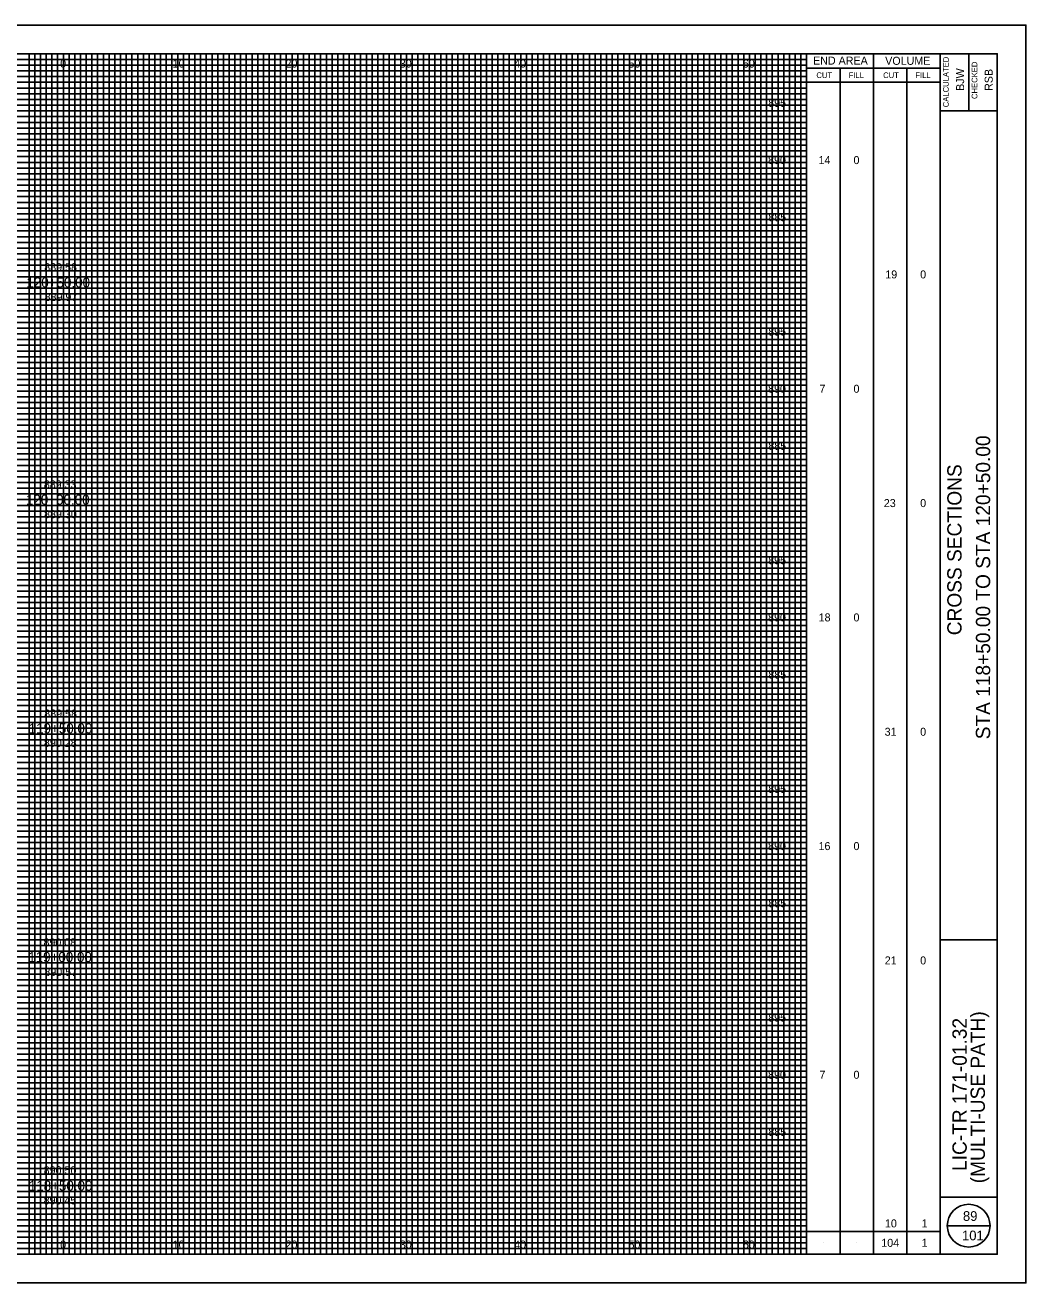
# Model space of a CAD drawing. Extents: x -10 to 160, y -2 to 3672.
# Drawn here: x 72.5 to 160, y 2297.5 to 2407.5 of the extents above; entities that cross this region are included whole.
import ezdxf

# ---------------------------------------------------------------- set-up
doc = ezdxf.new("R2010")
doc.units = 0
for name, color, linetype in [('SH_Border', 7, 'Continuous'), ('SH_Cut_Line', 7, 'Continuous'), ('SH_Data', 7, 'Continuous'), ('SH_Major_Grid_Line', 7, 'Continuous'), ('SH_Minor_Grid_Line', 7, 'Continuous'), ('SH_Text', 7, 'Continuous'), ('TX_P_10', 7, 'Continuous'), ('TX_X_10', 7, 'Continuous')]:
    doc.layers.add(name, color=color, linetype=linetype)

msp = doc.modelspace()

# ---------------------------------------------------------------- linework, layer by layer
at = {"layer": 'SH_Border'}
for p, q in [((152.5, 2300), (152.5, 2405)), ((155, 2405), (155, 2400)), ((152.5, 2400), (157.5, 2400)), ((152.5, 2327.5), (157.5, 2327.5)), ((152.5, 2305), (157.5, 2305))]:
    msp.add_line(p, q, dxfattribs=at)
msp.add_lwpolyline([(0, 2405), (157.5, 2405), (157.5, 2300), (0, 2300)], close=True, dxfattribs=at)
at = {"layer": 'SH_Cut_Line'}
msp.add_lwpolyline([(-10, 2297.5), (160, 2297.5), (160, 2407.5), (-10, 2407.5)], close=True, dxfattribs=at)
at = {"layer": 'SH_Data'}
for p, q in [((140.83, 2300), (140.83, 2405)), ((146.67, 2300), (146.67, 2405)), ((140.83, 2403.75), (152.5, 2403.75)), ((143.75, 2300), (143.75, 2403.75)), ((149.58, 2300), (149.58, 2403.75)), ((140.83, 2402.5), (152.5, 2402.5)), ((153.12, 2302.5), (156.88, 2302.5)), ((140.83, 2302), (152.5, 2302)), ((142.29, 2301), (142.29, 2301)), ((145.21, 2301), (145.21, 2301)), ((148.12, 2301), (148.12, 2301)), ((151.04, 2301), (151.04, 2301))]:
    msp.add_line(p, q, dxfattribs=at)
msp.add_circle((155, 2302.5), 1.87, dxfattribs=at)
at = {"layer": 'SH_Major_Grid_Line'}
for p, q in [((75.83, 2300), (75.83, 2405)), ((80.83, 2300), (80.83, 2405)), ((85.83, 2300), (85.83, 2405)), ((90.83, 2300), (90.83, 2405)), ((95.83, 2300), (95.83, 2405)), ((100.83, 2300), (100.83, 2405)), ((105.83, 2300), (105.83, 2405)), ((110.83, 2300), (110.83, 2405)), ((115.83, 2300), (115.83, 2405)), ((120.83, 2300), (120.83, 2405)), ((125.83, 2300), (125.83, 2405)), ((130.83, 2300), (130.83, 2405)), ((135.83, 2300), (135.83, 2405)), ((5.83, 2400), (140.83, 2400)), ((5.83, 2395), (140.83, 2395)), ((5.83, 2390), (140.83, 2390)), ((5.83, 2385), (140.83, 2385)), ((5.83, 2380), (140.83, 2380)), ((5.83, 2375), (140.83, 2375)), ((5.83, 2370), (140.83, 2370)), ((5.83, 2365), (140.83, 2365)), ((5.83, 2360), (140.83, 2360)), ((5.83, 2355), (140.83, 2355)), ((5.83, 2350), (140.83, 2350)), ((5.83, 2345), (140.83, 2345)), ((5.83, 2340), (140.83, 2340)), ((5.83, 2335), (140.83, 2335)), ((5.83, 2330), (140.83, 2330)), ((5.83, 2325), (140.83, 2325)), ((5.83, 2320), (140.83, 2320)), ((5.83, 2315), (140.83, 2315)), ((5.83, 2310), (140.83, 2310)), ((5.83, 2305), (140.83, 2305))]:
    msp.add_line(p, q, dxfattribs=at)
at = {"layer": 'SH_Minor_Grid_Line'}
for p, q in [((72.83, 2300), (72.83, 2405)), ((73.33, 2300), (73.33, 2405)), ((73.83, 2300), (73.83, 2405)), ((74.33, 2300), (74.33, 2405)), ((74.83, 2300), (74.83, 2405)), ((75.33, 2300), (75.33, 2405)), ((76.33, 2300), (76.33, 2405)), ((76.83, 2300), (76.83, 2405)), ((77.33, 2300), (77.33, 2405)), ((77.83, 2300), (77.83, 2405)), ((78.33, 2300), (78.33, 2405)), ((78.83, 2300), (78.83, 2405)), ((79.33, 2300), (79.33, 2405)), ((79.83, 2300), (79.83, 2405)), ((80.33, 2300), (80.33, 2405)), ((81.33, 2300), (81.33, 2405)), ((81.83, 2300), (81.83, 2405)), ((82.33, 2300), (82.33, 2405)), ((82.83, 2300), (82.83, 2405)), ((83.33, 2300), (83.33, 2405)), ((83.83, 2300), (83.83, 2405)), ((84.33, 2300), (84.33, 2405)), ((84.83, 2300), (84.83, 2405)), ((85.33, 2300), (85.33, 2405)), ((86.33, 2300), (86.33, 2405)), ((86.83, 2300), (86.83, 2405)), ((87.33, 2300), (87.33, 2405)), ((87.83, 2300), (87.83, 2405)), ((88.33, 2300), (88.33, 2405)), ((88.83, 2300), (88.83, 2405)), ((89.33, 2300), (89.33, 2405)), ((89.83, 2300), (89.83, 2405)), ((90.33, 2300), (90.33, 2405)), ((91.33, 2300), (91.33, 2405)), ((91.83, 2300), (91.83, 2405)), ((92.33, 2300), (92.33, 2405)), ((92.83, 2300), (92.83, 2405)), ((93.33, 2300), (93.33, 2405)), ((93.83, 2300), (93.83, 2405)), ((94.33, 2300), (94.33, 2405)), ((94.83, 2300), (94.83, 2405)), ((95.33, 2300), (95.33, 2405)), ((96.33, 2300), (96.33, 2405)), ((96.83, 2300), (96.83, 2405)), ((97.33, 2300), (97.33, 2405)), ((97.83, 2300), (97.83, 2405)), ((98.33, 2300), (98.33, 2405)), ((98.83, 2300), (98.83, 2405)), ((99.33, 2300), (99.33, 2405)), ((99.83, 2300), (99.83, 2405)), ((100.33, 2300), (100.33, 2405)), ((101.33, 2300), (101.33, 2405)), ((101.83, 2300), (101.83, 2405)), ((102.33, 2300), (102.33, 2405)), ((102.83, 2300), (102.83, 2405)), ((103.33, 2300), (103.33, 2405)), ((103.83, 2300), (103.83, 2405)), ((104.33, 2300), (104.33, 2405)), ((104.83, 2300), (104.83, 2405)), ((105.33, 2300), (105.33, 2405)), ((106.33, 2300), (106.33, 2405)), ((106.83, 2300), (106.83, 2405)), ((107.33, 2300), (107.33, 2405)), ((107.83, 2300), (107.83, 2405)), ((108.33, 2300), (108.33, 2405)), ((108.83, 2300), (108.83, 2405)), ((109.33, 2300), (109.33, 2405)), ((109.83, 2300), (109.83, 2405)), ((110.33, 2300), (110.33, 2405)), ((111.33, 2300), (111.33, 2405)), ((111.83, 2300), (111.83, 2405)), ((112.33, 2300), (112.33, 2405)), ((112.83, 2300), (112.83, 2405)), ((113.33, 2300), (113.33, 2405)), ((113.83, 2300), (113.83, 2405)), ((114.33, 2300), (114.33, 2405)), ((114.83, 2300), (114.83, 2405)), ((115.33, 2300), (115.33, 2405)), ((116.33, 2300), (116.33, 2405)), ((116.83, 2300), (116.83, 2405)), ((117.33, 2300), (117.33, 2405)), ((117.83, 2300), (117.83, 2405)), ((118.33, 2300), (118.33, 2405)), ((118.83, 2300), (118.83, 2405)), ((119.33, 2300), (119.33, 2405)), ((119.83, 2300), (119.83, 2405)), ((120.33, 2300), (120.33, 2405)), ((121.33, 2300), (121.33, 2405)), ((121.83, 2300), (121.83, 2405)), ((122.33, 2300), (122.33, 2405)), ((122.83, 2300), (122.83, 2405)), ((123.33, 2300), (123.33, 2405)), ((123.83, 2300), (123.83, 2405)), ((124.33, 2300), (124.33, 2405)), ((124.83, 2300), (124.83, 2405)), ((125.33, 2300), (125.33, 2405)), ((126.33, 2300), (126.33, 2405)), ((126.83, 2300), (126.83, 2405)), ((127.33, 2300), (127.33, 2405)), ((127.83, 2300), (127.83, 2405)), ((128.33, 2300), (128.33, 2405)), ((128.83, 2300), (128.83, 2405)), ((129.33, 2300), (129.33, 2405)), ((129.83, 2300), (129.83, 2405)), ((130.33, 2300), (130.33, 2405)), ((131.33, 2300), (131.33, 2405)), ((131.83, 2300), (131.83, 2405)), ((132.33, 2300), (132.33, 2405)), ((132.83, 2300), (132.83, 2405)), ((133.33, 2300), (133.33, 2405)), ((133.83, 2300), (133.83, 2405)), ((134.33, 2300), (134.33, 2405)), ((134.83, 2300), (134.83, 2405)), ((135.33, 2300), (135.33, 2405)), ((136.33, 2300), (136.33, 2405)), ((136.83, 2300), (136.83, 2405)), ((137.33, 2300), (137.33, 2405)), ((137.83, 2300), (137.83, 2405)), ((138.33, 2300), (138.33, 2405)), ((138.83, 2300), (138.83, 2405)), ((139.33, 2300), (139.33, 2405)), ((139.83, 2300), (139.83, 2405)), ((140.33, 2300), (140.33, 2405)), ((5.83, 2404.5), (140.83, 2404.5)), ((5.83, 2404), (140.83, 2404)), ((5.83, 2403.5), (140.83, 2403.5)), ((5.83, 2403), (140.83, 2403)), ((5.83, 2402.5), (140.83, 2402.5)), ((5.83, 2402), (140.83, 2402)), ((5.83, 2401.5), (140.83, 2401.5)), ((5.83, 2401), (140.83, 2401)), ((5.83, 2400.5), (140.83, 2400.5)), ((5.83, 2399.5), (140.83, 2399.5)), ((5.83, 2399), (140.83, 2399)), ((5.83, 2398.5), (140.83, 2398.5)), ((5.83, 2398), (140.83, 2398)), ((5.83, 2397.5), (140.83, 2397.5)), ((5.83, 2397), (140.83, 2397)), ((5.83, 2396.5), (140.83, 2396.5)), ((5.83, 2396), (140.83, 2396)), ((5.83, 2395.5), (140.83, 2395.5)), ((5.83, 2394.5), (140.83, 2394.5)), ((5.83, 2394), (140.83, 2394)), ((5.83, 2393.5), (140.83, 2393.5)), ((5.83, 2393), (140.83, 2393)), ((5.83, 2392.5), (140.83, 2392.5)), ((5.83, 2392), (140.83, 2392)), ((5.83, 2391.5), (140.83, 2391.5)), ((5.83, 2391), (140.83, 2391)), ((5.83, 2390.5), (140.83, 2390.5)), ((5.83, 2389.5), (140.83, 2389.5)), ((5.83, 2389), (140.83, 2389)), ((5.83, 2388.5), (140.83, 2388.5)), ((5.83, 2388), (140.83, 2388)), ((5.83, 2387.5), (140.83, 2387.5)), ((5.83, 2387), (140.83, 2387)), ((5.83, 2386.5), (140.83, 2386.5)), ((5.83, 2386), (140.83, 2386)), ((5.83, 2385.5), (140.83, 2385.5)), ((5.83, 2384.5), (140.83, 2384.5)), ((5.83, 2384), (140.83, 2384)), ((5.83, 2383.5), (140.83, 2383.5)), ((5.83, 2383), (140.83, 2383)), ((5.83, 2382.5), (140.83, 2382.5)), ((5.83, 2382), (140.83, 2382)), ((5.83, 2381.5), (140.83, 2381.5)), ((5.83, 2381), (140.83, 2381)), ((5.83, 2380.5), (140.83, 2380.5)), ((5.83, 2379.5), (140.83, 2379.5)), ((5.83, 2379), (140.83, 2379)), ((5.83, 2378.5), (140.83, 2378.5)), ((5.83, 2378), (140.83, 2378)), ((5.83, 2377.5), (140.83, 2377.5)), ((5.83, 2377), (140.83, 2377)), ((5.83, 2376.5), (140.83, 2376.5)), ((5.83, 2376), (140.83, 2376)), ((5.83, 2375.5), (140.83, 2375.5)), ((5.83, 2374.5), (140.83, 2374.5)), ((5.83, 2374), (140.83, 2374)), ((5.83, 2373.5), (140.83, 2373.5)), ((5.83, 2373), (140.83, 2373)), ((5.83, 2372.5), (140.83, 2372.5)), ((5.83, 2372), (140.83, 2372)), ((5.83, 2371.5), (140.83, 2371.5)), ((5.83, 2371), (140.83, 2371)), ((5.83, 2370.5), (140.83, 2370.5)), ((5.83, 2369.5), (140.83, 2369.5)), ((5.83, 2369), (140.83, 2369)), ((5.83, 2368.5), (140.83, 2368.5)), ((5.83, 2368), (140.83, 2368)), ((5.83, 2367.5), (140.83, 2367.5)), ((5.83, 2367), (140.83, 2367)), ((5.83, 2366.5), (140.83, 2366.5)), ((5.83, 2366), (140.83, 2366)), ((5.83, 2365.5), (140.83, 2365.5)), ((5.83, 2364.5), (140.83, 2364.5)), ((5.83, 2364), (140.83, 2364)), ((5.83, 2363.5), (140.83, 2363.5)), ((5.83, 2363), (140.83, 2363)), ((5.83, 2362.5), (140.83, 2362.5)), ((5.83, 2362), (140.83, 2362)), ((5.83, 2361.5), (140.83, 2361.5)), ((5.83, 2361), (140.83, 2361)), ((5.83, 2360.5), (140.83, 2360.5)), ((5.83, 2359.5), (140.83, 2359.5)), ((5.83, 2359), (140.83, 2359)), ((5.83, 2358.5), (140.83, 2358.5)), ((5.83, 2358), (140.83, 2358)), ((5.83, 2357.5), (140.83, 2357.5)), ((5.83, 2357), (140.83, 2357)), ((5.83, 2356.5), (140.83, 2356.5)), ((5.83, 2356), (140.83, 2356)), ((5.83, 2355.5), (140.83, 2355.5)), ((5.83, 2354.5), (140.83, 2354.5)), ((5.83, 2354), (140.83, 2354)), ((5.83, 2353.5), (140.83, 2353.5)), ((5.83, 2353), (140.83, 2353)), ((5.83, 2352.5), (140.83, 2352.5)), ((5.83, 2352), (140.83, 2352)), ((5.83, 2351.5), (140.83, 2351.5)), ((5.83, 2351), (140.83, 2351)), ((5.83, 2350.5), (140.83, 2350.5)), ((5.83, 2349.5), (140.83, 2349.5)), ((5.83, 2349), (140.83, 2349)), ((5.83, 2348.5), (140.83, 2348.5)), ((5.83, 2348), (140.83, 2348)), ((5.83, 2347.5), (140.83, 2347.5)), ((5.83, 2347), (140.83, 2347)), ((5.83, 2346.5), (140.83, 2346.5)), ((5.83, 2346), (140.83, 2346)), ((5.83, 2345.5), (140.83, 2345.5)), ((5.83, 2344.5), (140.83, 2344.5)), ((5.83, 2344), (140.83, 2344)), ((5.83, 2343.5), (140.83, 2343.5)), ((5.83, 2343), (140.83, 2343)), ((5.83, 2342.5), (140.83, 2342.5)), ((5.83, 2342), (140.83, 2342)), ((5.83, 2341.5), (140.83, 2341.5)), ((5.83, 2341), (140.83, 2341)), ((5.83, 2340.5), (140.83, 2340.5)), ((5.83, 2339.5), (140.83, 2339.5)), ((5.83, 2339), (140.83, 2339)), ((5.83, 2338.5), (140.83, 2338.5)), ((5.83, 2338), (140.83, 2338)), ((5.83, 2337.5), (140.83, 2337.5)), ((5.83, 2337), (140.83, 2337)), ((5.83, 2336.5), (140.83, 2336.5)), ((5.83, 2336), (140.83, 2336)), ((5.83, 2335.5), (140.83, 2335.5)), ((5.83, 2334.5), (140.83, 2334.5)), ((5.83, 2334), (140.83, 2334)), ((5.83, 2333.5), (140.83, 2333.5)), ((5.83, 2333), (140.83, 2333)), ((5.83, 2332.5), (140.83, 2332.5)), ((5.83, 2332), (140.83, 2332)), ((5.83, 2331.5), (140.83, 2331.5)), ((5.83, 2331), (140.83, 2331)), ((5.83, 2330.5), (140.83, 2330.5)), ((5.83, 2329.5), (140.83, 2329.5)), ((5.83, 2329), (140.83, 2329)), ((5.83, 2328.5), (140.83, 2328.5)), ((5.83, 2328), (140.83, 2328)), ((5.83, 2327.5), (140.83, 2327.5)), ((5.83, 2327), (140.83, 2327)), ((5.83, 2326.5), (140.83, 2326.5)), ((5.83, 2326), (140.83, 2326)), ((5.83, 2325.5), (140.83, 2325.5)), ((5.83, 2324.5), (140.83, 2324.5)), ((5.83, 2324), (140.83, 2324)), ((5.83, 2323.5), (140.83, 2323.5)), ((5.83, 2323), (140.83, 2323)), ((5.83, 2322.5), (140.83, 2322.5)), ((5.83, 2322), (140.83, 2322)), ((5.83, 2321.5), (140.83, 2321.5)), ((5.83, 2321), (140.83, 2321)), ((5.83, 2320.5), (140.83, 2320.5)), ((5.83, 2319.5), (140.83, 2319.5)), ((5.83, 2319), (140.83, 2319)), ((5.83, 2318.5), (140.83, 2318.5)), ((5.83, 2318), (140.83, 2318)), ((5.83, 2317.5), (140.83, 2317.5)), ((5.83, 2317), (140.83, 2317)), ((5.83, 2316.5), (140.83, 2316.5)), ((5.83, 2316), (140.83, 2316)), ((5.83, 2315.5), (140.83, 2315.5)), ((5.83, 2314.5), (140.83, 2314.5)), ((5.83, 2314), (140.83, 2314)), ((5.83, 2313.5), (140.83, 2313.5)), ((5.83, 2313), (140.83, 2313)), ((5.83, 2312.5), (140.83, 2312.5)), ((5.83, 2312), (140.83, 2312)), ((5.83, 2311.5), (140.83, 2311.5)), ((5.83, 2311), (140.83, 2311)), ((5.83, 2310.5), (140.83, 2310.5)), ((5.83, 2309.5), (140.83, 2309.5)), ((5.83, 2309), (140.83, 2309)), ((5.83, 2308.5), (140.83, 2308.5)), ((5.83, 2308), (140.83, 2308)), ((5.83, 2307.5), (140.83, 2307.5)), ((5.83, 2307), (140.83, 2307)), ((5.83, 2306.5), (140.83, 2306.5)), ((5.83, 2306), (140.83, 2306)), ((5.83, 2305.5), (140.83, 2305.5)), ((5.83, 2304.5), (140.83, 2304.5)), ((5.83, 2304), (140.83, 2304)), ((5.83, 2303.5), (140.83, 2303.5)), ((5.83, 2303), (140.83, 2303)), ((5.83, 2302.5), (140.83, 2302.5)), ((5.83, 2302), (140.83, 2302)), ((5.83, 2301.5), (140.83, 2301.5)), ((5.83, 2301), (140.83, 2301)), ((5.83, 2300.5), (140.83, 2300.5))]:
    msp.add_line(p, q, dxfattribs=at)

# ---------------------------------------------------------------- texts
at = {"layer": 'SH_Data'}
for s, height, p in [('END AREA', 0.7, (141.39, 2404.05)), ('VOLUME', 0.7, (147.7, 2404.03)), ('CUT', 0.5, (141.68, 2402.87)), ('FILL', 0.5, (144.5, 2402.87)), ('CUT', 0.5, (147.52, 2402.87)), ('FILL', 0.5, (150.34, 2402.87)), ('89', 0.85, (154.5, 2302.92)), ('101', 0.85, (154.42, 2301.22))]:
    msp.add_text(s, height=height, dxfattribs=at).set_placement(p)
for s, height, p in [('CALCULATED', 0.5, (153.26, 2400.32)), ('BJW', 0.7, (154.6, 2401.75)), ('CHECKED', 0.5, (155.76, 2401.04)), ('RSB', 0.7, (157.1, 2401.75)), ('STA 118+50.00 TO STA 120+50.00', 1.25, (156.88, 2345.04)), ('CROSS SECTIONS', 1.25, (154.38, 2354.14)), ('(MULTI-USE PATH)', 1.25, (156.42, 2306.21)), ('LIC-TR 171-01.32', 1.25, (154.83, 2307.29))]:
    msp.add_text(s, height=height, rotation=90, dxfattribs=at).set_placement(p)
at = {"layer": 'SH_Text'}
for s, height, p in [('0', 0.7, (75.55, 2403.79)), ('10', 0.7, (85.39, 2403.79)), ('20', 0.7, (95.26, 2403.79)), ('30', 0.7, (105.25, 2403.79)), ('40', 0.7, (115.25, 2403.79)), ('50', 0.7, (125.25, 2403.79)), ('60', 0.7, (135.25, 2403.79)), ('895', 0.7, (137.47, 2400.35)), ('890', 0.7, (137.46, 2395.35)), ('14', 0.7, (141.87, 2395.35)), ('0', 0.7, (144.93, 2395.35)), ('885', 0.7, (137.48, 2390.35)), ('19', 0.7, (147.71, 2385.35)), ('0', 0.7, (150.76, 2385.35)), ('120+50.00', 0.875, (72.6, 2384.56)), ('895', 0.7, (137.47, 2380.35)), ('890', 0.7, (137.46, 2375.35)), ('7', 0.7, (141.95, 2375.35)), ('0', 0.7, (144.93, 2375.35)), ('885', 0.7, (137.48, 2370.35)), ('120+00.00', 0.875, (72.56, 2365.56)), ('23', 0.7, (147.58, 2365.35)), ('0', 0.7, (150.76, 2365.35)), ('895', 0.7, (137.47, 2360.35)), ('890', 0.7, (137.46, 2355.35)), ('18', 0.7, (141.88, 2355.35)), ('0', 0.7, (144.93, 2355.35)), ('885', 0.7, (137.48, 2350.35)), ('119+50.00', 0.875, (72.8, 2345.56)), ('31', 0.7, (147.65, 2345.35)), ('0', 0.7, (150.76, 2345.35)), ('895', 0.7, (137.47, 2340.35)), ('890', 0.7, (137.46, 2335.35)), ('16', 0.7, (141.87, 2335.35)), ('0', 0.7, (144.93, 2335.35)), ('885', 0.7, (137.48, 2330.35)), ('119+00.00', 0.875, (72.76, 2325.56)), ('21', 0.7, (147.66, 2325.35)), ('0', 0.7, (150.76, 2325.35)), ('895', 0.7, (137.47, 2320.35)), ('890', 0.7, (137.46, 2315.35)), ('7', 0.7, (141.95, 2315.35)), ('0', 0.7, (144.93, 2315.35)), ('885', 0.7, (137.48, 2310.35)), ('118+50.00', 0.875, (72.81, 2305.56)), ('10', 0.7, (147.68, 2302.35)), ('1', 0.7, (150.88, 2302.35)), ('0', 0.7, (75.55, 2300.5)), ('10', 0.7, (85.39, 2300.5)), ('20', 0.7, (95.26, 2300.5)), ('30', 0.7, (105.25, 2300.5)), ('40', 0.7, (115.25, 2300.5)), ('50', 0.7, (125.25, 2300.5)), ('60', 0.7, (135.25, 2300.5)), ('104', 0.7, (147.36, 2300.65)), ('1', 0.7, (150.88, 2300.65))]:
    msp.add_text(s, height=height, dxfattribs=at).set_placement(p)
at = {"layer": 'TX_P_10'}
for s, p in [('889.58', (74.16, 2385.98)), ('889.33', (74.12, 2366.99)), ('889.58', (74.16, 2346.94)), ('890.08', (74.09, 2326.93)), ('890.50', (74.11, 2307))]:
    msp.add_text(s, height=0.7, dxfattribs=at).set_placement(p)
at = {"layer": 'TX_X_10'}
for s, p in [('889.97', (74.19, 2383.37)), ('889.30', (74.14, 2364.38)), ('890.28', (74.13, 2344.38)), ('890.57', (74.17, 2324.34)), ('890.45', (74.1, 2304.36))]:
    msp.add_text(s, height=0.7, dxfattribs=at).set_placement(p)

doc.saveas('drawing.dxf')
